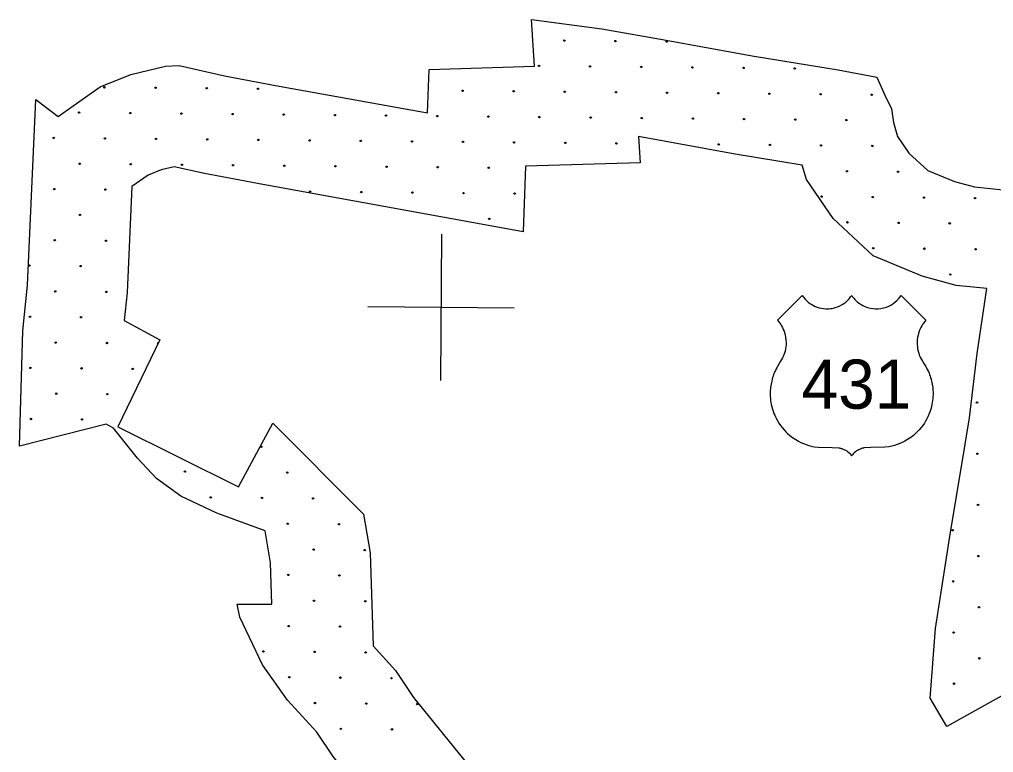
# Model space of a CAD drawing. Extents: x 1612280 to 1883141, y 560852 to 780851.
# Drawn here: x 1719614 to 1726937, y 695386 to 700897 of the extents above; entities that cross this region are included whole.
import ezdxf

# ---------------------------------------------------------------- set-up
doc = ezdxf.new("R2010")
doc.units = 0
for name, color, linetype in [('DESIGN - EROSION CONTROL - Devices', 7, 'Continuous'), ('DESIGN - SCRATCH - User 1', 7, 'Continuous'), ('SURVEY - DRAINAGE - Bridge Deck with Text', 7, 'Continuous'), ('SURVEY - DRAINAGE - Bridge Hydraulic Data - Points - Locators', 7, 'Continuous')]:
    doc.layers.add(name, color=color, linetype=linetype)

msp = doc.modelspace()

# ---------------------------------------------------------------- linework, layer by layer
at = {"layer": 'DESIGN - EROSION CONTROL - Devices'}
for centre in [(1723710, 700738.4), (1723710, 700738.4), (1724094.6, 700734.6), (1724094.6, 700734.6), (1724479.1, 700730.9), (1724479.1, 700730.9), (1723519.6, 700548), (1723519.6, 700548), (1723904.2, 700544.2), (1723904.2, 700544.2), (1724288.7, 700540.5), (1724288.7, 700540.5), (1724673.3, 700536.8), (1724673.3, 700536.8), (1725057.8, 700533), (1725057.8, 700533), (1725442.4, 700529.3), (1725442.4, 700529.3), (1720252.8, 700387.4), (1720252.8, 700387.4), (1720637.3, 700383.7), (1720637.3, 700383.7), (1721021.9, 700380), (1721021.9, 700380), (1721406.4, 700376.2), (1721406.4, 700376.2), (1722944.7, 700361.3), (1722944.7, 700361.3), (1723329.2, 700357.6), (1723329.2, 700357.6), (1723713.8, 700353.8), (1723713.8, 700353.8), (1724098.3, 700350.1), (1724098.3, 700350.1), (1724482.9, 700346.4), (1724482.9, 700346.4), (1724867.4, 700342.6), (1724867.4, 700342.6), (1725252, 700338.9), (1725252, 700338.9), (1725636.5, 700335.2), (1725636.5, 700335.2), (1726021.1, 700331.4), (1726021.1, 700331.4), (1720062.4, 700197), (1720062.4, 700197), (1720446.9, 700193.3), (1720446.9, 700193.3), (1720831.5, 700189.5), (1720831.5, 700189.5), (1721216, 700185.8), (1721216, 700185.8), (1721600.6, 700182.1), (1721600.6, 700182.1), (1721985.1, 700178.3), (1721985.1, 700178.3), (1722369.7, 700174.6), (1722369.7, 700174.6), (1722754.2, 700170.9), (1722754.2, 700170.9), (1723138.8, 700167.1), (1723138.8, 700167.1), (1723523.4, 700163.4), (1723523.4, 700163.4), (1723907.9, 700159.7), (1723907.9, 700159.7), (1724292.5, 700155.9), (1724292.5, 700155.9), (1724677, 700152.2), (1724677, 700152.2), (1725061.6, 700148.5), (1725061.6, 700148.5), (1725446.1, 700144.7), (1725446.1, 700144.7), (1725830.7, 700141), (1725830.7, 700141), (1719872, 700006.6), (1719872, 700006.6), (1720256.5, 700002.9), (1720256.5, 700002.9), (1720641.1, 699999.1), (1720641.1, 699999.1), (1721025.6, 699995.4), (1721025.6, 699995.4), (1721410.2, 699991.7), (1721410.2, 699991.7), (1721794.7, 699987.9), (1721794.7, 699987.9), (1722179.3, 699984.2), (1722179.3, 699984.2), (1722563.8, 699980.5), (1722563.8, 699980.5), (1722948.4, 699976.7), (1722948.4, 699976.7), (1723332.9, 699973), (1723332.9, 699973), (1723717.5, 699969.3), (1723717.5, 699969.3), (1724102, 699965.5), (1724102, 699965.5), (1724871.2, 699958.1), (1724871.2, 699958.1), (1725255.7, 699954.3), (1725255.7, 699954.3), (1725640.3, 699950.6), (1725640.3, 699950.6), (1726024.8, 699946.9), (1726024.8, 699946.9), (1720066.1, 699812.5), (1720066.1, 699812.5), (1720450.7, 699808.7), (1720450.7, 699808.7), (1720835.2, 699805), (1720835.2, 699805), (1721219.8, 699801.3), (1721219.8, 699801.3), (1721604.3, 699797.5), (1721604.3, 699797.5), (1721988.9, 699793.8), (1721988.9, 699793.8), (1722373.4, 699790.1), (1722373.4, 699790.1), (1722758, 699786.3), (1722758, 699786.3), (1723142.5, 699782.6), (1723142.5, 699782.6), (1725834.4, 699756.5), (1725834.4, 699756.5), (1726219, 699752.7), (1726219, 699752.7), (1719875.7, 699622.1), (1719875.7, 699622.1), (1720260.3, 699618.3), (1720260.3, 699618.3), (1721798.5, 699603.4), (1721798.5, 699603.4), (1722183, 699599.7), (1722183, 699599.7), (1722567.6, 699595.9), (1722567.6, 699595.9), (1722952.1, 699592.2), (1722952.1, 699592.2), (1723336.7, 699588.4), (1723336.7, 699588.4), (1725644, 699566), (1725644, 699566), (1726028.5, 699562.3), (1726028.5, 699562.3), (1726413.1, 699558.6), (1726413.1, 699558.6), (1726797.7, 699554.8), (1726797.7, 699554.8), (1720069.8, 699427.9), (1720069.8, 699427.9), (1723146.3, 699398), (1723146.3, 699398), (1725838.1, 699371.9), (1725838.1, 699371.9), (1726222.7, 699368.2), (1726222.7, 699368.2), (1726607.2, 699364.4), (1726607.2, 699364.4), (1719879.4, 699237.5), (1719879.4, 699237.5), (1720264, 699233.8), (1720264, 699233.8), (1726032.3, 699177.8), (1726032.3, 699177.8), (1726416.8, 699174), (1726416.8, 699174), (1726801.4, 699170.3), (1726801.4, 699170.3), (1719689, 699047.1), (1719689, 699047.1), (1720073.6, 699043.4), (1720073.6, 699043.4), (1726611, 698979.9), (1726611, 698979.9), (1719883.2, 698852.9), (1719883.2, 698852.9), (1720267.7, 698849.2), (1720267.7, 698849.2), (1719692.8, 698662.5), (1719692.8, 698662.5), (1720077.3, 698658.8), (1720077.3, 698658.8), (1719886.9, 698468.4), (1719886.9, 698468.4), (1720271.5, 698464.7), (1720271.5, 698464.7), (1719696.5, 698278), (1719696.5, 698278), (1720081, 698274.2), (1720081, 698274.2), (1720465.6, 698270.5), (1720465.6, 698270.5), (1719890.6, 698083.8), (1719890.6, 698083.8), (1720275.2, 698080.1), (1720275.2, 698080.1), (1726812.6, 698016.6), (1726812.6, 698016.6), (1719700.2, 697893.4), (1719700.2, 697893.4), (1720084.8, 697889.7), (1720084.8, 697889.7), (1721432.6, 697684.4), (1721432.6, 697684.4), (1726816.3, 697632.1), (1726816.3, 697632.1), (1720857.6, 697497.7), (1720857.6, 697497.7), (1721626.7, 697490.2), (1721626.7, 697490.2), (1721051.8, 697303.5), (1721051.8, 697303.5), (1721436.3, 697299.8), (1721436.3, 697299.8), (1721820.9, 697296.1), (1721820.9, 697296.1), (1726820.1, 697247.5), (1726820.1, 697247.5), (1721630.5, 697105.7), (1721630.5, 697105.7), (1722015, 697101.9), (1722015, 697101.9), (1726629.6, 697057.1), (1726629.6, 697057.1), (1721824.6, 696911.5), (1721824.6, 696911.5), (1722209.2, 696907.8), (1722209.2, 696907.8), (1726823.8, 696863), (1726823.8, 696863), (1721634.2, 696721.1), (1721634.2, 696721.1), (1722018.7, 696717.4), (1722018.7, 696717.4), (1726633.4, 696672.6), (1726633.4, 696672.6), (1721828.3, 696527), (1721828.3, 696527), (1722212.9, 696523.2), (1722212.9, 696523.2), (1726827.5, 696478.4), (1726827.5, 696478.4), (1721637.9, 696336.6), (1721637.9, 696336.6), (1722022.5, 696332.8), (1722022.5, 696332.8), (1726637.1, 696288), (1726637.1, 696288), (1721447.5, 696146.1), (1721447.5, 696146.1), (1721832.1, 696142.4), (1721832.1, 696142.4), (1722216.6, 696138.7), (1722216.6, 696138.7), (1726831.3, 696093.9), (1726831.3, 696093.9), (1721641.7, 695952), (1721641.7, 695952), (1722026.2, 695948.3), (1722026.2, 695948.3), (1722410.8, 695944.5), (1722410.8, 695944.5), (1726640.8, 695903.5), (1726640.8, 695903.5), (1721835.8, 695757.9), (1721835.8, 695757.9), (1722220.4, 695754.1), (1722220.4, 695754.1), (1722604.9, 695750.4), (1722604.9, 695750.4), (1722029.9, 695563.7), (1722029.9, 695563.7), (1722414.5, 695560), (1722414.5, 695560)]:
    msp.add_circle(centre, 5.28, dxfattribs=at)
msp.add_arc((1720656, 698460.9), 5.28, 62.23192, 246.15547, dxfattribs=at)
at = {"layer": 'DESIGN - SCRATCH - User 1'}
for points in [[(1723485.2, 700546.1), (1723464, 700897.4)], [(1723464, 700897.4), (1723991.9, 700826.3), (1724475.9, 700741.6), (1725122.2, 700623.1), (1725768.6, 700518.1), (1726059.7, 700463.9)], [(1723485.2, 700546.1), (1723464, 700897.4)], [(1723464, 700897.4), (1723991.9, 700826.3), (1724475.9, 700741.6), (1725122.2, 700623.1), (1725768.6, 700518.1), (1726059.7, 700463.9)], [(1719905.1, 700167.1), (1720017.5, 700248.9), (1720221.8, 700392), (1720451.6, 700484), (1720712.1, 700545.3), (1720814.3, 700550.4), (1721156.5, 700473.8), (1721539.6, 700402.2), (1722681.3, 700194.2)], [(1719905.1, 700167.1), (1720017.5, 700248.9), (1720221.8, 700392), (1720451.6, 700484), (1720712.1, 700545.3), (1720814.3, 700550.4), (1721156.5, 700473.8), (1721539.6, 700402.2), (1722681.3, 700194.2)], [(1722681.3, 700194.2), (1722693.1, 700522.4)], [(1722681.3, 700194.2), (1722693.1, 700522.4)], [(1722693.1, 700522.4), (1723485.2, 700546.1)], [(1722693.1, 700522.4), (1723485.2, 700546.1)], [(1726059.7, 700463.9), (1726120.2, 700327.7), (1726170.3, 700225.1), (1726185.6, 700122.5), (1726216.1, 700017.7), (1726301.2, 699893.3), (1726443, 699762.3), (1726643.8, 699679.3), (1726794.3, 699637.8), (1727125.9, 699605.1), (1727507.7, 699552.7), (1727747.7, 699522.1)], [(1726059.7, 700463.9), (1726120.2, 700327.7), (1726170.3, 700225.1), (1726185.6, 700122.5), (1726216.1, 700017.7), (1726301.2, 699893.3), (1726443, 699762.3), (1726643.8, 699679.3), (1726794.3, 699637.8), (1727125.9, 699605.1), (1727507.7, 699552.7), (1727747.7, 699522.1)], [(1719614, 697688.3), (1719639.5, 698557.1), (1719675.2, 698899.6), (1719736.5, 700294.9)], [(1719614, 697688.3), (1719639.5, 698557.1), (1719675.2, 698899.6), (1719736.5, 700294.9)], [(1719736.5, 700294.9), (1719905.1, 700167.1)], [(1719736.5, 700294.9), (1719905.1, 700167.1)], [(1725497.7, 699802.2), (1724994.5, 699884), (1724268.6, 700017.1)], [(1724268.6, 700017.1), (1724280.5, 699819.5)], [(1725497.7, 699802.2), (1724994.5, 699884), (1724268.6, 700017.1)], [(1724268.6, 700017.1), (1724280.5, 699819.5)], [(1723399.6, 699300.9), (1721403.5, 699664.6), (1721005.6, 699739), (1720777.2, 699790.1), (1720678.2, 699766.8), (1720581, 699727.9), (1720458.6, 699642.2)], [(1723399.6, 699300.9), (1721403.5, 699664.6), (1721005.6, 699739), (1720777.2, 699790.1), (1720678.2, 699766.8), (1720581, 699727.9), (1720458.6, 699642.2)], [(1723417.4, 699793.7), (1723399.6, 699300.9)], [(1723417.4, 699793.7), (1723399.6, 699300.9)], [(1724280.5, 699819.5), (1723417.4, 699793.7)], [(1724280.5, 699819.5), (1723417.4, 699793.7)], [(1726887, 698875), (1726656.8, 698897.7), (1726400, 698968.5), (1726032.7, 699120.3), (1725730, 699399.8), (1725529.6, 699693), (1725497.7, 699802.2)], [(1726887, 698875), (1726656.8, 698897.7), (1726400, 698968.5), (1726032.7, 699120.3), (1725730, 699399.8), (1725529.6, 699693), (1725497.7, 699802.2)], [(1720458.6, 699642.2), (1720423.5, 698844.1), (1720401.6, 698634.3)], [(1720458.6, 699642.2), (1720423.5, 698844.1), (1720401.6, 698634.3)], [(1726460.7, 695793.3), (1726499.6, 696318.6), (1726613.8, 697042.5), (1726697, 697536.5), (1726756.1, 697901.5), (1726812.7, 698385), (1726887, 698875)], [(1726460.7, 695793.3), (1726499.6, 696318.6), (1726613.8, 697042.5), (1726697, 697536.5), (1726756.1, 697901.5), (1726812.7, 698385), (1726887, 698875)], [(1720401.6, 698634.3), (1720669.4, 698488.2)], [(1720401.6, 698634.3), (1720669.4, 698488.2)], [(1720669.4, 698488.2), (1720353.6, 697835.1)], [(1720669.4, 698488.2), (1720353.6, 697835.1)], [(1720265.2, 697854.4), (1719614, 697688.3)], [(1720265.2, 697854.4), (1719614, 697688.3)], [(1721460.4, 697051.9), (1721097.7, 697184.8), (1720827, 697312.6), (1720643.2, 697445.5), (1720500.1, 697598.8), (1720321.4, 697823.7), (1720265.2, 697854.4)], [(1721460.4, 697051.9), (1721097.7, 697184.8), (1720827, 697312.6), (1720643.2, 697445.5), (1720500.1, 697598.8), (1720321.4, 697823.7), (1720265.2, 697854.4)], [(1720353.6, 697835.1), (1721260.4, 697383.6)], [(1720353.6, 697835.1), (1721260.4, 697383.6)], [(1721260.4, 697383.6), (1721519.8, 697861.8)], [(1721260.4, 697383.6), (1721519.8, 697861.8)], [(1721519.8, 697861.8), (1722199.7, 697177.7), (1722249.2, 696887.2), (1722272.1, 696187.3)], [(1721519.8, 697861.8), (1722199.7, 697177.7), (1722249.2, 696887.2), (1722272.1, 696187.3)], [(1721511.5, 696499.9), (1721501.3, 696811.7), (1721460.4, 697051.9)], [(1721511.5, 696499.9), (1721501.3, 696811.7), (1721460.4, 697051.9)], [(1722225.3, 695042), (1721971.2, 695355.1), (1721848.6, 695539.1), (1721629, 695779.3), (1721440, 696045.1), (1721271.4, 696402.8), (1721251, 696499.9)], [(1721251, 696499.9), (1721511.5, 696499.9)], [(1722225.3, 695042), (1721971.2, 695355.1), (1721848.6, 695539.1), (1721629, 695779.3), (1721440, 696045.1), (1721271.4, 696402.8), (1721251, 696499.9)], [(1721251, 696499.9), (1721511.5, 696499.9)], [(1722272.1, 696187.3), (1722440.9, 696002.8), (1722575.7, 695800.3), (1723028.5, 695242.5)], [(1722272.1, 696187.3), (1722440.9, 696002.8), (1722575.7, 695800.3), (1723028.5, 695242.5)], [(1727688.9, 695396.5), (1727301, 695978.7), (1726587, 695581.7), (1726460.7, 695793.3)], [(1727688.9, 695396.5), (1727301, 695978.7), (1726587, 695581.7), (1726460.7, 695793.3)]]:
    msp.add_lwpolyline(points, dxfattribs=at)
at = {"layer": 'SURVEY - DRAINAGE - Bridge Deck with Text'}
for points in [[(1725311.7, 698636.1), (1725499.2, 698822.5), (1725508.9, 698808.7), (1725521.3, 698794), (1725533.3, 698781.8), (1725544.5, 698772), (1725556.9, 698762.6), (1725569.8, 698754.2), (1725582.2, 698747.2), (1725596.7, 698740.2), (1725609.7, 698735), (1725626.2, 698729.8), (1725641.8, 698726.2), (1725658.3, 698723.6), (1725676, 698722.1), (1725684, 698722), (1725692.1, 698722.1), (1725699.9, 698722.5), (1725710.1, 698723.4), (1725720.5, 698724.9), (1725733.9, 698727.5), (1725746.4, 698730.7), (1725764.6, 698736.8), (1725781.8, 698744.4), (1725798.3, 698753.3), (1725812.2, 698762.3), (1725826, 698772.8), (1725839.3, 698784.7), (1725851.3, 698797.3), (1725862.5, 698811.3), (1725870.4, 698822.5), (1725877.2, 698812.6), (1725886, 698801.4), (1725893.9, 698792.4), (1725903.2, 698783), (1725914.9, 698772.6), (1725927.3, 698763.1), (1725940.5, 698754.4), (1725954.1, 698746.7), (1725970.1, 698739.3), (1725988.7, 698732.4), (1726010, 698726.8), (1726030.8, 698723.4), (1726049, 698722.1), (1726068.8, 698722.3), (1726089, 698724.4), (1726109.2, 698728.4), (1726131.5, 698735.3), (1726149.2, 698742.6), (1726163.8, 698750), (1726180.8, 698760.5), (1726195, 698771.1), (1726210.8, 698785.1), (1726221.6, 698796.4), (1726231.4, 698808.3), (1726241.5, 698822.5), (1726428.3, 698636.1)], [(1725311.7, 698636.1), (1725499.2, 698822.5), (1725508.9, 698808.7), (1725521.3, 698794), (1725533.3, 698781.8), (1725544.5, 698772), (1725556.9, 698762.6), (1725569.8, 698754.2), (1725582.2, 698747.2), (1725596.7, 698740.2), (1725609.7, 698735), (1725626.2, 698729.8), (1725641.8, 698726.2), (1725658.3, 698723.6), (1725676, 698722.1), (1725684, 698722), (1725692.1, 698722.1), (1725699.9, 698722.5), (1725710.1, 698723.4), (1725720.5, 698724.9), (1725733.9, 698727.5), (1725746.4, 698730.7), (1725764.6, 698736.8), (1725781.8, 698744.4), (1725798.3, 698753.3), (1725812.2, 698762.3), (1725826, 698772.8), (1725839.3, 698784.7), (1725851.3, 698797.3), (1725862.5, 698811.3), (1725870.4, 698822.5), (1725877.2, 698812.6), (1725886, 698801.4), (1725893.9, 698792.4), (1725903.2, 698783), (1725914.9, 698772.6), (1725927.3, 698763.1), (1725940.5, 698754.4), (1725954.1, 698746.7), (1725970.1, 698739.3), (1725988.7, 698732.4), (1726010, 698726.8), (1726030.8, 698723.4), (1726049, 698722.1), (1726068.8, 698722.3), (1726089, 698724.4), (1726109.2, 698728.4), (1726131.5, 698735.3), (1726149.2, 698742.6), (1726163.8, 698750), (1726180.8, 698760.5), (1726195, 698771.1), (1726210.8, 698785.1), (1726221.6, 698796.4), (1726231.4, 698808.3), (1726241.5, 698822.5), (1726428.3, 698636.1)], [(1725311.7, 698636.1), (1725320.8, 698625.4), (1725329.1, 698614.7), (1725336.7, 698603.6), (1725343, 698593.3), (1725349.8, 698580.9), (1725356.3, 698566.9), (1725361.9, 698552.9), (1725367, 698537.5), (1725370.9, 698523), (1725374, 698507.1), (1725376.3, 698489.3), (1725377.4, 698467.7), (1725377.1, 698451.2), (1725375.7, 698435.3), (1725373.6, 698421.3), (1725369.7, 698403.1), (1725365.8, 698389.3), (1725361.2, 698376.1), (1725356.3, 698364), (1725351.5, 698353.6), (1725343.8, 698339.9), (1725336.5, 698327.3), (1725326, 698309.7), (1725313.2, 698288.6), (1725309.5, 698282.6), (1725303.6, 698271.6), (1725297, 698258.4), (1725292.8, 698249.3), (1725288, 698238), (1725283.9, 698227.7), (1725280, 698216.7), (1725276.1, 698205), (1725272.5, 698192.4), (1725269, 698179), (1725266.5, 698167.8), (1725264.1, 698155.7), (1725262.2, 698143.8), (1725260.5, 698131.1), (1725259.3, 698119.5), (1725258.5, 698107.9), (1725258, 698097.1), (1725257.8, 698085.9), (1725257.9, 698073.5), (1725258.4, 698061.9), (1725259.4, 698047.4), (1725261.1, 698032.3), (1725263.4, 698017), (1725266.1, 698002.2), (1725269.8, 697986), (1725275.1, 697966.9), (1725279.7, 697952.3), (1725286.2, 697934.7), (1725292.1, 697921.1), (1725297.2, 697909.4), (1725304.5, 697894.8), (1725314.3, 697877.3), (1725323.4, 697862.6), (1725335.4, 697845.1), (1725347.9, 697828.8), (1725361.7, 697812.5), (1725376.2, 697797.2), (1725388.7, 697785.2), (1725405.6, 697770.5), (1725425.3, 697755.1), (1725449.5, 697738.8), (1725469.8, 697727), (1725489.2, 697717.1), (1725507.3, 697709), (1725528.1, 697700.9), (1725547.3, 697694.6), (1725566.7, 697689.3), (1725576.6, 697687), (1725589.2, 697685.3), (1725619.3, 697682.7), (1725724.9, 697679.4), (1725772.6, 697676.9), (1725777.1, 697676.3), (1725781.9, 697675.2), (1725787.1, 697674), (1725792.1, 697672.5), (1725796.9, 697670.9), (1725801.5, 697669.2), (1725806.8, 697667.1), (1725811.2, 697665.1), (1725816.3, 697662.6), (1725820.2, 697660.6), (1725824.2, 697658.3), (1725832.8, 697652.9), (1725841.9, 697646.2), (1725850.5, 697638.8), (1725858.1, 697631.2), (1725864.5, 697623.9), (1725870, 697615.7)], [(1725311.7, 698636.1), (1725320.8, 698625.4), (1725329.1, 698614.7), (1725336.7, 698603.6), (1725343, 698593.3), (1725349.8, 698580.9), (1725356.3, 698566.9), (1725361.9, 698552.9), (1725367, 698537.5), (1725370.9, 698523), (1725374, 698507.1), (1725376.3, 698489.3), (1725377.4, 698467.7), (1725377.1, 698451.2), (1725375.7, 698435.3), (1725373.6, 698421.3), (1725369.7, 698403.1), (1725365.8, 698389.3), (1725361.2, 698376.1), (1725356.3, 698364), (1725351.5, 698353.6), (1725343.8, 698339.9), (1725336.5, 698327.3), (1725326, 698309.7), (1725313.2, 698288.6), (1725309.5, 698282.6), (1725303.6, 698271.6), (1725297, 698258.4), (1725292.8, 698249.3), (1725288, 698238), (1725283.9, 698227.7), (1725280, 698216.7), (1725276.1, 698205), (1725272.5, 698192.4), (1725269, 698179), (1725266.5, 698167.8), (1725264.1, 698155.7), (1725262.2, 698143.8), (1725260.5, 698131.1), (1725259.3, 698119.5), (1725258.5, 698107.9), (1725258, 698097.1), (1725257.8, 698085.9), (1725257.9, 698073.5), (1725258.4, 698061.9), (1725259.4, 698047.4), (1725261.1, 698032.3), (1725263.4, 698017), (1725266.1, 698002.2), (1725269.8, 697986), (1725275.1, 697966.9), (1725279.7, 697952.3), (1725286.2, 697934.7), (1725292.1, 697921.1), (1725297.2, 697909.4), (1725304.5, 697894.8), (1725314.3, 697877.3), (1725323.4, 697862.6), (1725335.4, 697845.1), (1725347.9, 697828.8), (1725361.7, 697812.5), (1725376.2, 697797.2), (1725388.7, 697785.2), (1725405.6, 697770.5), (1725425.3, 697755.1), (1725449.5, 697738.8), (1725469.8, 697727), (1725489.2, 697717.1), (1725507.3, 697709), (1725528.1, 697700.9), (1725547.3, 697694.6), (1725566.7, 697689.3), (1725576.6, 697687), (1725589.2, 697685.3), (1725619.3, 697682.7), (1725724.9, 697679.4), (1725772.6, 697676.9), (1725777.1, 697676.3), (1725781.9, 697675.2), (1725787.1, 697674), (1725792.1, 697672.5), (1725796.9, 697670.9), (1725801.5, 697669.2), (1725806.8, 697667.1), (1725811.2, 697665.1), (1725816.3, 697662.6), (1725820.2, 697660.6), (1725824.2, 697658.3), (1725832.8, 697652.9), (1725841.9, 697646.2), (1725850.5, 697638.8), (1725858.1, 697631.2), (1725864.5, 697623.9), (1725870, 697615.7)], [(1726428.3, 698636.1), (1726419.2, 698625.4), (1726411, 698614.8), (1726403.3, 698603.6), (1726397.1, 698593.3), (1726390.2, 698580.9), (1726383.7, 698567), (1726378.1, 698552.9), (1726373, 698537.5), (1726369.2, 698523.1), (1726366, 698507.1), (1726363.7, 698489.4), (1726362.6, 698467.7), (1726363, 698451.3), (1726364.4, 698435.3), (1726366.4, 698421.3), (1726370.3, 698403.1), (1726374.3, 698389.3), (1726378.8, 698376.1), (1726383.7, 698364), (1726388.5, 698353.7), (1726396.3, 698339.9), (1726403.5, 698327.3), (1726414, 698309.7), (1726426.8, 698288.6), (1726430.5, 698282.6), (1726436.5, 698271.6), (1726443, 698258.4), (1726447.2, 698249.3), (1726452, 698238), (1726456.1, 698227.7), (1726460, 698216.7), (1726463.9, 698205), (1726467.6, 698192.4), (1726471.1, 698179), (1726473.6, 698167.8), (1726475.9, 698155.7), (1726477.8, 698143.8), (1726479.6, 698131.1), (1726480.8, 698119.5), (1726481.6, 698108), (1726482.1, 698097.1), (1726482.2, 698086), (1726482.1, 698073.5), (1726481.7, 698061.9), (1726480.6, 698047.4), (1726478.9, 698032.3), (1726476.7, 698017), (1726473.9, 698002.3), (1726470.3, 697986), (1726465, 697966.9), (1726460.3, 697952.3), (1726453.9, 697934.7), (1726447.9, 697921.1), (1726442.9, 697909.5), (1726435.6, 697894.9), (1726425.8, 697877.4), (1726416.7, 697862.7), (1726404.7, 697845.1), (1726392.1, 697828.8), (1726378.3, 697812.5), (1726363.9, 697797.2), (1726351.4, 697785.2), (1726334.5, 697770.5), (1726314.7, 697755.1), (1726290.5, 697738.8), (1726270.3, 697727), (1726250.9, 697717.1), (1726232.8, 697709), (1726212, 697700.9), (1726192.7, 697694.6), (1726173.4, 697689.3), (1726163.5, 697687), (1726150.8, 697685.3), (1726120.8, 697682.7), (1726015.2, 697679.4), (1725967.4, 697676.9), (1725963, 697676.4), (1725958.1, 697675.3), (1725953, 697674), (1725948, 697672.5), (1725943.2, 697670.9), (1725938.6, 697669.2), (1725933.3, 697667.1), (1725928.9, 697665.1), (1725923.8, 697662.6), (1725919.9, 697660.6), (1725915.8, 697658.3), (1725907.3, 697652.9), (1725898.2, 697646.2), (1725889.6, 697638.8), (1725882, 697631.2), (1725875.6, 697623.9), (1725870, 697615.7)], [(1726428.3, 698636.1), (1726419.2, 698625.4), (1726411, 698614.8), (1726403.3, 698603.6), (1726397.1, 698593.3), (1726390.2, 698580.9), (1726383.7, 698567), (1726378.1, 698552.9), (1726373, 698537.5), (1726369.2, 698523.1), (1726366, 698507.1), (1726363.7, 698489.4), (1726362.6, 698467.7), (1726363, 698451.3), (1726364.4, 698435.3), (1726366.4, 698421.3), (1726370.3, 698403.1), (1726374.3, 698389.3), (1726378.8, 698376.1), (1726383.7, 698364), (1726388.5, 698353.7), (1726396.3, 698339.9), (1726403.5, 698327.3), (1726414, 698309.7), (1726426.8, 698288.6), (1726430.5, 698282.6), (1726436.5, 698271.6), (1726443, 698258.4), (1726447.2, 698249.3), (1726452, 698238), (1726456.1, 698227.7), (1726460, 698216.7), (1726463.9, 698205), (1726467.6, 698192.4), (1726471.1, 698179), (1726473.6, 698167.8), (1726475.9, 698155.7), (1726477.8, 698143.8), (1726479.6, 698131.1), (1726480.8, 698119.5), (1726481.6, 698108), (1726482.1, 698097.1), (1726482.2, 698086), (1726482.1, 698073.5), (1726481.7, 698061.9), (1726480.6, 698047.4), (1726478.9, 698032.3), (1726476.7, 698017), (1726473.9, 698002.3), (1726470.3, 697986), (1726465, 697966.9), (1726460.3, 697952.3), (1726453.9, 697934.7), (1726447.9, 697921.1), (1726442.9, 697909.5), (1726435.6, 697894.9), (1726425.8, 697877.4), (1726416.7, 697862.7), (1726404.7, 697845.1), (1726392.1, 697828.8), (1726378.3, 697812.5), (1726363.9, 697797.2), (1726351.4, 697785.2), (1726334.5, 697770.5), (1726314.7, 697755.1), (1726290.5, 697738.8), (1726270.3, 697727), (1726250.9, 697717.1), (1726232.8, 697709), (1726212, 697700.9), (1726192.7, 697694.6), (1726173.4, 697689.3), (1726163.5, 697687), (1726150.8, 697685.3), (1726120.8, 697682.7), (1726015.2, 697679.4), (1725967.4, 697676.9), (1725963, 697676.4), (1725958.1, 697675.3), (1725953, 697674), (1725948, 697672.5), (1725943.2, 697670.9), (1725938.6, 697669.2), (1725933.3, 697667.1), (1725928.9, 697665.1), (1725923.8, 697662.6), (1725919.9, 697660.6), (1725915.8, 697658.3), (1725907.3, 697652.9), (1725898.2, 697646.2), (1725889.6, 697638.8), (1725882, 697631.2), (1725875.6, 697623.9), (1725870, 697615.7)]]:
    msp.add_lwpolyline(points, dxfattribs=at)
at = {"layer": 'SURVEY - DRAINAGE - Bridge Hydraulic Data - Points - Locators'}
for p, q in [((1722787.9, 699282.2), (1722778.1, 698182.2)), ((1722787.9, 699282.2), (1722778.1, 698182.2)), ((1723333, 698727.3), (1722233, 698737.2)), ((1723333, 698727.3), (1722233, 698737.2))]:
    msp.add_line(p, q, dxfattribs=at)

# ---------------------------------------------------------------- texts
at = {"layer": 'SURVEY - DRAINAGE - Bridge Deck with Text'}
msp.add_text('431', height=369.6, rotation=0.00128, dxfattribs=at).set_placement((1725494.3, 697970.6))
msp.add_text('431', height=369.6, rotation=0.00128, dxfattribs=at).set_placement((1725494.3, 697970.6))

doc.saveas('drawing.dxf')
